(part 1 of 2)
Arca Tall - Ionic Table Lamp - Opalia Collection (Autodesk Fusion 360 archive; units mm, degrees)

design "Marble Base - Ionic Table Lamp - Ketra Ready - 120V - Opalia Collection" references "Marble Base - Ionic Table Lamp - Ketra Ready - 120V", "Ketra - A20 Tunable Lamp", "Arca Tall", "Chinois", "Arca Petite", "Trove - TL", "Facet Petite"
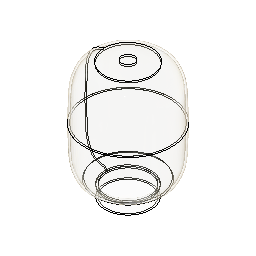
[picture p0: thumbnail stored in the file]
component_insert "Component Insert2"
component_insert "Component Insert3"
component_insert "Component Insert4"
component_insert "Component Insert5"
position "Position1"
component_insert "Component Insert6"
component_insert "Component Insert7"
component_insert "Component Insert8"

design "Arca Petite"
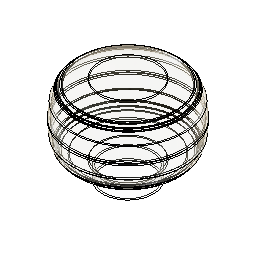
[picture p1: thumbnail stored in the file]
sketch "Sketch1" plane through (0, 0, 0) normal (0, 1, 0) x axis (1, 0, 0)
  line L1 (0, 101.6) -> (0, -101.6)
  line L2 (127, 0) -> (-127, 0)
  line L3 (63.5, 101.6) -> (-63.5, 101.6)
  perpendicular L1 L2
  parallel L2 L3
sketch "Sketch2" plane through (0, 0, 0) normal (0, 1, 0) x axis (1, 0, 0)
  line L1 (0, 101.6) -> (0, -101.6)
  line L2 (0, -76.2) -> (0, 101.6)
  line L3 (127, 0) -> (-127, 0)
  line L4 (114.3, 0) -> (-114.3, 0)
  line L5 (50.8, 101.6) -> (50.8, 63.5)
  line L6 (-50.8, 101.6) -> (50.8, 101.6)
  line L7 (-50.8, 63.5) -> (-50.8, 101.6)
  line L8 (63.5, 101.6) -> (-63.5, 101.6)
  line L9 (114.3, -76.2) -> (114.3, 63.5)
  line L10 (-114.3, -76.2) -> (114.3, -76.2)
  line L11 (-114.3, 63.5) -> (-114.3, -76.2)
  line L12 (-50.8, 63.5) -> (-114.3, 63.5)
  line L13 (114.3, 63.5) -> (50.8, 63.5)
  point P2 (0, 101.6)
  point P5 (0, 101.6)
  point P6 (0, -76.2)
  point P9 (-114.3, 0)
  point P10 (114.3, 0)
  point P11 (50.8, 101.6)
  point P19 (50.8, 63.5)
  coincident P2 P5
  coincident L1 P6
  coincident L3 P9
  coincident L3 P10
  vertical L5
  horizontal L6
  vertical L7
  coincident P11 L8
  horizontal L12
  vertical L9
  horizontal L10
  vertical L11
  coincident P19 L12
  collinear L12 L13
derived_base_feature "Derived Base Feature"
revolve "Revolve1" sketch "Sketch4" AlongAngle 360 bodies "Arca Petite"
shell "Shell1" innerThickness 3.81
component_from_bodies "Body->Comp"
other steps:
base_feature "Base Feature" bodies "Arca Petite"
create_component "CreateComponent1"
remove_body "RemoveBody1"
named bodies: "Arca Petite"

design "Neoprene Pad"
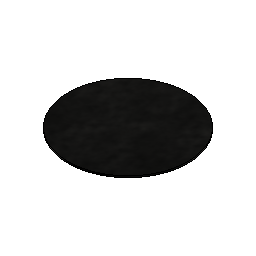
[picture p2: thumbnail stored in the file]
sketch "Sketch1" plane through (0, 0, 0) normal (0, 0, 1) x axis (1, 0, 0)
  circle C1 centre (0, 0) radius 57.15
  point P1 (0, 0)
  point P2 (0, 0)
  coincident P1 P2
extrude "Extrude1" new body sketch "Sketch1" along normal blind 1.5875 bodies "Neoprene Pad"
component_from_bodies "Body->Comp"
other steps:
base_feature "Base Feature" bodies "Neoprene Pad"
create_component "CreateComponent1"
remove_body "RemoveBody1"
named bodies: "Neoprene Pad"

design "T9 - Bulb"
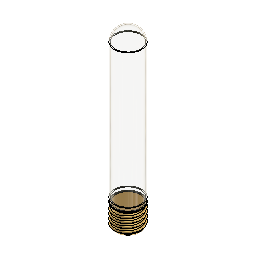
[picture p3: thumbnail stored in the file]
sketch "Sketch1" plane through (0, 0, 0) normal (0, 1, 0) x axis (1, 0, 0)
  line L1 (0, -166.37) -> (0, 0)
  line L2 (13.97, -13.97) -> (13.97, -152.4)
  line L3 (-13.97, -152.4) -> (-13.97, -13.97)
  line L4 (0, 0) -> (0, -166.37)
  line L5 (12.97, -13.97) -> (12.97, -152.4)
  line L6 (-12.97, -152.4) -> (-12.97, -13.97)
  line L7 (-12.3978, -10.16) -> (-13.4404, -10.16)
  line L8 (13.4404, -10.16) -> (12.3978, -10.16)
  arc A1 centre (0, -152.4) radius 13.97 clockwise from (13.97, -152.4) to (-13.97, -152.4)
  arc A2 centre (0, -152.4) radius 12.97 clockwise from (12.97, -152.4) to (-12.97, -152.4)
  arc A3 centre (0, -13.97) radius 13.97 clockwise from (13.4404, -10.16) to (13.97, -13.97)
  arc A4 centre (0, -13.97) radius 13.97 clockwise from (-13.97, -13.97) to (-13.4404, -10.16)
  arc A5 centre (0, -13.97) radius 12.97 clockwise from (12.3978, -10.16) to (12.97, -13.97)
  arc A6 centre (0, -13.97) radius 12.97 clockwise from (-12.97, -13.97) to (-12.3978, -10.16)
  point P1 (0, 0)
  point P2 (0, 0)
  point P3 (0, -166.37)
  point P10 (0, 0)
  point P17 (13.4404, -10.16)
  point P19 (12.3978, -10.16)
  point P4 (13.97, -152.4)
  point P5 (13.97, -13.97)
  coincident P1 P2
  vertical L1
  tangent L2 A3
  tangent L3 A3
  parallel L2 L3
  tangent L3 A1
  tangent L2 A1
  midpoint P3 A1
  coincident P1 P10
  perpendicular L1 L7
  coincident P17 L7
  concentric A3 A4
  coincident P10 A3
  concentric A1 A2
  tangent L5 A2
  tangent L5 A5
  tangent L6 A5
  tangent L6 A2
  coincident P19 L7
  concentric A5 A6
  collinear L7 L8
  dimension "d6" distance L2 L3 = 27.94
  dimension "d7" distance P4 P5 = 138.43
revolve "Revolve1" sketch "Sketch1" AlongAngle 360 bodies "T9"
derived_base_feature "Derived Base Feature" bodies "E26 Base"
align "Align1"
move "Move1"
component_from_bodies "Body->Comp1"
component_from_bodies "Body->Comp2"
copy_paste "CutPaste1"
copy_paste "CutPaste2"
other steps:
base_feature "Base Feature1" bodies "T9"
base_feature "Base Feature1" bodies "E26 Base"
create_component "CreateComponent1"
create_component "CreateComponent2"
remove_body "RemoveBody1"
create_component "CreateComponent3"
remove_body "RemoveBody2"
remove_instance "RemoveInstance1"
remove_instance "RemoveInstance2"
named bodies: "T9", "E26 Base"

design "Marble Base - Silicone Gasket"
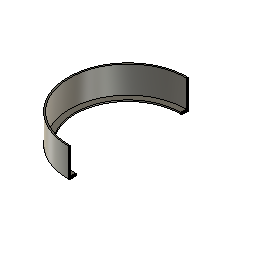
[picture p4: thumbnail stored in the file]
sketch "Sketch1" plane through (0, 0, 0) normal (0, 0, 1) x axis (1, 0, 0)
  circle C1 centre (0, 0) radius 53.34
  point P1 (0, 0)
  point P2 (0, 0)
  coincident P1 P2
extrude "Extrude1" new body sketch "Sketch1" along normal blind 25.4 bodies "Silicone Gasket"
shell "Shell1" innerThickness 1.27
sketch "Sketch2" plane through (0, 0, 1.27) normal (0, 0, 1) x axis (-1, 0, 0)
  circle C1 centre (0, 0) radius 52.07
  circle C2 centre (0, 0) radius 46.99
  concentric C1 C2
extrude "Extrude2" cut sketch "Sketch2" profile of C2 against normal blind 12.7
component_from_bodies "Body->Comp"
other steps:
base_feature "Base Feature" bodies "Silicone Gasket"
create_component "CreateComponent1"
remove_body "RemoveBody1"
named bodies: "Silicone Gasket"

design "2-Pole Plug End"
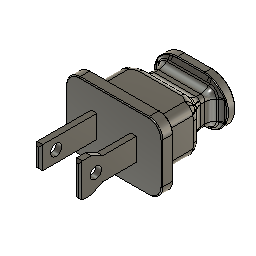
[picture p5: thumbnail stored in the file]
sketch "Sketch1" plane through (0, 0, 0) normal (0, 1, 0) x axis (1, 0, 0)
  line L1 (9.6837, 9.525) -> (-9.6837, 9.525)
  line L2 (13.4938, -5.715) -> (13.4938, 5.715)
  line L3 (-9.6837, -9.525) -> (9.6837, -9.525)
  line L4 (-13.4937, 5.715) -> (-13.4937, -5.715)
  line L5 (13.4938, -9.525) -> (-13.4937, 9.525)
  line L6 (-13.4937, -9.525) -> (13.4938, 9.525)
  arc A1 centre (-9.6837, -5.715) radius 3.81 clockwise from (-9.6837, -9.525) to (-13.4937, -5.715)
  arc A2 centre (9.6837, -5.715) radius 3.81 clockwise from (13.4938, -5.715) to (9.6837, -9.525)
  arc A3 centre (9.6837, 5.715) radius 3.81 clockwise from (9.6837, 9.525) to (13.4938, 5.715)
  arc A4 centre (-9.6837, 5.715) radius 3.81 clockwise from (-13.4937, 5.715) to (-9.6837, 9.525)
  point P6 (0, 0)
  point P1 (0, 0)
  point P5 (-13.4937, -9.525)
  point P4 (13.4938, -9.525)
  point P3 (13.4938, 9.525)
  point P2 (-13.4937, 9.525)
  horizontal L1
  perpendicular L1 L2
  parallel L1 L3
  parallel L2 L4
  coincident L5 P6
  coincident L6 P6
  coincident P1 P6
  coincident P5 L4
  coincident P5 L3
  tangent L4 A1
  tangent L3 A1
  coincident P4 L3
  coincident P4 L2
  tangent L3 A2
  tangent L2 A2
  equal A1 A2
  coincident P3 L2
  coincident P3 L1
  tangent L2 A3
  tangent L1 A3
  equal A1 A3
  coincident P2 L1
  coincident P2 L4
  tangent L1 A4
  tangent L4 A4
  equal A1 A4
  dimension "d1" distance P4 P5 = 26.9875
  dimension "d2" distance P2 P5 = 19.05
  dimension "d3" radius A1 = 3.81
extrude "Extrude1" new body sketch "Sketch1" profile of L1 L2 L3 L4 A1 A2 A3 A4 along normal blind 3.175
sketch "Sketch2" plane through (0, 3.175, 0) normal (0, 1, 0) x axis (-1, 0, 0)
  line L1 (9.6837, -9.525) -> (-9.6837, -9.525)
  line L2 (13.4937, 5.715) -> (13.4937, -5.715)
  line L3 (-9.6837, 9.525) -> (9.6837, 9.525)
  line L4 (-13.4938, -5.715) -> (-13.4938, 5.715)
  line L5 (10.16, -6.35) -> (-10.16, -6.35)
  line L6 (10.16, 6.35) -> (10.16, -6.35)
  line L7 (-10.16, 6.35) -> (10.16, 6.35)
  line L8 (-10.16, -6.35) -> (-10.16, 6.35)
  line L9 (10.16, 6.35) -> (-10.16, -6.35)
  line L10 (-10.16, 6.35) -> (10.16, -6.35)
  arc A1 centre (-9.6837, -5.715) radius 3.81 clockwise from (-9.6837, -9.525) to (-13.4938, -5.715)
  arc A2 centre (9.6837, -5.715) radius 3.81 clockwise from (13.4937, -5.715) to (9.6837, -9.525)
  arc A3 centre (9.6837, 5.715) radius 3.81 clockwise from (9.6837, 9.525) to (13.4937, 5.715)
  arc A4 centre (-9.6837, 5.715) radius 3.81 clockwise from (-13.4938, 5.715) to (-9.6837, 9.525)
  point P18 (0, 0)
  point P1 (0, 0)
  horizontal L5
  perpendicular L5 L6
  parallel L5 L7
  parallel L6 L8
  coincident L9 P18
  coincident L10 P18
  coincident P1 P18
extrude "Extrude2" add sketch "Sketch2" profile of L5 L6 L7 L8 along normal blind 9.525
sketch "Sketch3" plane through (0, 12.7, 0) normal (0, 1, 0) x axis (-1, 0, 0)
  line L1 (-10.16, -6.35) -> (-10.16, 6.35)
  line L2 (10.16, -6.35) -> (-10.16, -6.35)
  line L3 (10.16, 6.35) -> (10.16, -6.35)
  line L4 (-10.16, 6.35) -> (10.16, 6.35)
  line L5 (-7.1437, 3.9688) -> (7.1437, 3.9688)
  line L6 (-7.1437, -3.9688) -> (-7.1437, 3.9688)
  line L7 (7.1437, -3.9688) -> (-7.1437, -3.9688)
  line L8 (7.1437, 3.9688) -> (7.1437, -3.9688)
  line L9 (-7.1437, -3.9688) -> (7.1437, 3.9688)
  line L10 (7.1437, -3.9688) -> (-7.1437, 3.9688)
  point P10 (0, 0)
  point P1 (0, 0)
  point P8 (-7.1437, -3.9688)
  point P9 (7.1437, -3.9688)
  point P7 (-7.1437, 3.9688)
  horizontal L5
  perpendicular L5 L6
  parallel L5 L7
  parallel L6 L8
  coincident L9 P10
  coincident L10 P10
  coincident P1 P10
  dimension "d8" distance P8 P9 = 14.2875
  dimension "d9" distance P7 P8 = 7.9375
extrude "Extrude3" add sketch "Sketch3" profile of L5 L6 L7 L8 along normal blind 11.1125
fillet "Fillet1" radius 2.286 1.27 0.254
chamfer "Chamfer1" distance 3.429
fillet "Fillet2" radius 2.54 1.905
sketch "Sketch4" plane through (0, 23.8125, 0) normal (0, 1, 0) x axis (-1, 0, 0)
  line L1 (-7.1437, -2.6987) -> (-7.1437, 2.6987)
  line L2 (5.8737, -3.9688) -> (-5.8737, -3.9688)
  line L3 (7.1437, 2.6987) -> (7.1437, -2.6987)
  line L4 (-5.8737, 3.9688) -> (5.8737, 3.9688)
  line L5 (-3.81, 6.604) -> (3.81, 6.604)
  line L6 (3.81, -6.604) -> (-3.81, -6.604)
  line L7 (-10.414, 0) -> (10.414, 0)
  arc A1 centre (-5.8737, 2.6987) radius 1.27 clockwise from (-7.1437, 2.6987) to (-5.8737, 3.9688)
  arc A2 centre (-5.8737, -2.6987) radius 1.27 clockwise from (-5.8737, -3.9688) to (-7.1437, -2.6987)
  arc A3 centre (5.8737, -2.6987) radius 1.27 clockwise from (7.1437, -2.6987) to (5.8737, -3.9688)
  arc A4 centre (5.8737, 2.6987) radius 1.27 clockwise from (5.8737, 3.9688) to (7.1437, 2.6987)
  arc A5 centre (-3.81, 0) radius 6.604 clockwise from (-3.81, -6.604) to (-3.81, 6.604)
  arc A6 centre (3.81, 0) radius 6.604 clockwise from (3.81, 6.604) to (3.81, -6.604)
  point P20 (10.414, 0)
  point P21 (-10.414, 0)
  tangent L5 A5
  tangent A5 L6
  parallel L5 L6
  tangent L6 A6
  tangent L5 A6
  midpoint A6 P20
  midpoint A5 P21
  perpendicular L1 L7
extrude "Extrude4" add sketch "Sketch4" profile of A1 L1 A2 L2 A3 L3 A4 L4 L5 A5 L6 A6 against normal blind 2.286
chamfer "Chamfer2" distance 1.778
fillet "Fillet3" radius 1.778
fillet "Fillet4" radius 0.254
fillet "Fillet5" radius 0.254
fillet "Fillet6" radius 0.254
fillet "Fillet7" radius 3.175
sketch "Sketch5" plane through (0, 0, 0) normal (0, -1, 0) x axis (1, 0, 0)
  line L1 (-13.2397, -5.715) -> (-13.2397, 5.715)
  line L2 (9.6837, -9.271) -> (-9.6837, -9.271)
  line L3 (13.2397, 5.715) -> (13.2397, -5.715)
  line L4 (-9.6837, 9.271) -> (9.6837, 9.271)
  line L5 (-6.35, -3.175) -> (-6.35, 3.175)
  line L6 (6.35, 3.175) -> (-6.35, -3.175)
  line L7 (-6.35, 3.175) -> (6.35, -3.175)
  line L8 (-4.7625, 3.175) -> (-6.35, 3.175)
  line L9 (-4.7625, -3.175) -> (-4.7625, 3.175)
  line L10 (-6.35, -3.175) -> (-4.7625, -3.175)
  line L11 (-6.35, 3.175) -> (-6.35, -3.175)
  line L12 (0, -3.302) -> (0, 3.81)
  line L13 (4.7625, -3.175) -> (4.7625, 3.175)
  line L14 (4.7625, 3.175) -> (6.35, 3.175)
  line L15 (6.35, -3.175) -> (6.35, 3.175)
  line L16 (6.35, -3.175) -> (4.7625, -3.175)
  arc A1 centre (-9.6837, 5.715) radius 3.556 clockwise from (-13.2397, 5.715) to (-9.6837, 9.271)
  arc A2 centre (-9.6837, -5.715) radius 3.556 clockwise from (-9.6837, -9.271) to (-13.2397, -5.715)
  arc A3 centre (9.6837, -5.715) radius 3.556 clockwise from (13.2397, -5.715) to (9.6837, -9.271)
  arc A4 centre (9.6837, 5.715) radius 3.556 clockwise from (9.6837, 9.271) to (13.2397, 5.715)
  point P18 (0, 0)
  point P1 (0, 0)
  point P14 (-6.35, -3.175)
  point P27 (6.35, -3.175)
  point P17 (-6.35, 3.175)
  point P26 (6.35, 3.175)
  point P19 (-4.7625, 3.175)
  point P24 (4.7625, 3.175)
  point P20 (-4.7625, -3.175)
  point P25 (4.7625, -3.175)
  point P21 (-6.35, -3.175)
  point P28 (6.35, -3.175)
  point P15 (6.35, -3.175)
  point P16 (6.35, 3.175)
  coincident L6 P18
  coincident L7 P18
  coincident P1 P18
  horizontal L8
  vertical L9
  horizontal L10
  vertical L11
  vertical L12
  symmetric P14 L12 P27
  symmetric P17 L12 P26
  symmetric P19 L12 P24
  symmetric P20 L12 P25
  symmetric P21 L12 P28
  dimension "d36" distance P15 P16 = 6.35
  dimension "d37" distance P17 P19 = 1.5875
extrude "Extrude5" add sketch "Sketch5" profile of L5 L8 L9 L10 L11 L13 L14 L15 L16 along normal blind 15.875
sketch "Sketch7" plane through (0, 0, 3.175) normal (0, 0, 1) x axis (-1, 0, 0)
  line L1 (-4.7625, 0) -> (-6.35, 0)
  line L2 (-4.7625, 15.875) -> (-4.7625, 0)
  line L3 (-6.35, 15.875) -> (-4.7625, 15.875)
  line L4 (-6.35, 0) -> (-6.35, 15.875)
  line L5 (-4.7625, 15.875) -> (-6.35, 15.875)
  line L6 (-4.7625, 9.525) -> (-4.7625, 15.875)
  line L7 (-6.35, 9.525) -> (-4.7625, 9.525)
  line L8 (-6.35, 15.875) -> (-6.35, 9.525)
  point P5 (-6.35, 15.875)
  point P6 (-6.35, 15.875)
  point P9 (-6.35, 9.525)
  horizontal L5
  vertical L6
  horizontal L7
  vertical L8
  coincident P5 P6
  dimension "d45" distance P6 P9 = 6.35
extrude "Extrude7" add sketch "Sketch7" profile of L2 L3 L4 L5 L6 L7 L8 against normal blind 7.9375 and along normal blind 1.5875
chamfer "Chamfer3" distance 0.508
chamfer "Chamfer4" distance 0.635 distance 0.635
sketch "Sketch6" plane through (6.35, 0, 0) normal (1, 0, 0) x axis (0, 1, 0)
  line L1 (0, -3.175) -> (-9.525, -3.175)
  line L2 (0, 3.175) -> (0, -3.175)
  line L3 (-9.525, 3.175) -> (0, 3.175)
  line L4 (-15.367, -4.6355) -> (-15.367, 4.6355)
  line L5 (-11.43, 0) -> (-16.002, 0)
  line L6 (-9.525, -4.7625) -> (-15.24, -4.7625)
  line L7 (-9.525, -3.175) -> (-9.525, -4.7625)
  line L8 (-9.525, 4.7625) -> (-9.525, 3.175)
  line L9 (-15.24, 4.7625) -> (-9.525, 4.7625)
  line L10 (-15.24, -4.7625) -> (-15.367, -4.6355)
  line L11 (-15.367, 4.6355) -> (-15.24, 4.7625)
  circle C1 centre (-11.43, 0) radius 1.5875
  point P9 (-11.43, 0)
  point P10 (-11.43, 0)
  perpendicular L4 L5
  coincident P9 P10
  dimension "d42" diameter C1 = 3.175
extrude "Extrude6" cut sketch "Sketch6" profile of C1 against normal blind 20.32
chamfer "Chamfer5" distance 3.175 distance 1.5875 distance 3.175 distance 1.5875
component_from_bodies "Body->Comp"
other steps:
base_feature "Base Feature" bodies "2-Pole Plug End"
create_component "CreateComponent1"
remove_body "RemoveBody1"
named bodies: "2-Pole Plug End"

design "Facet Petite"
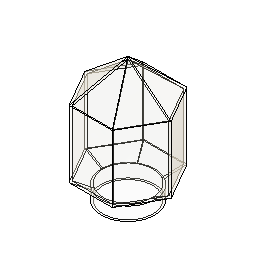
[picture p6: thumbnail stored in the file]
sketch "Sketch7" plane through (0, 0, 0) normal (1, 0, 0) x axis (0, 1, 0)
sketch "Sketch8" plane through (0, 0, 0) normal (0, 0, 1) x axis (1, 0, 0)
  circle C1 centre (0, 0) radius 50.8
  point P1 (0, 0)
  point P2 (0, 0)
  coincident P1 P2
  dimension "d17" diameter C1 = 101.6
extrude "Extrude5" new body sketch "Sketch8" along normal blind 25.4 and against normal blind 25.4
work_plane "WorkPlane1" AlongDistance 17.78
sketch "Sketch10" plane through (0, 0, 25.4) normal (0, 0, 1) x axis (-1, 0, 0)
  circle C1 centre (0, 0) radius 50.8
sketch "Sketch12" plane through (0, 0, 43.18) normal (0, 0, 1) x axis (1, 0, 0)
  line L1 (-82.1223, 0) -> (-41.0612, 71.12)
  line L2 (-41.0612, -71.12) -> (-82.1223, 0)
  line L3 (41.0612, -71.12) -> (-41.0612, -71.12)
  line L4 (82.1223, 0) -> (41.0612, -71.12)
  line L5 (41.0612, 71.12) -> (82.1223, 0)
  line L6 (-41.0612, 71.12) -> (41.0612, 71.12)
  point P1 (0, 0)
  point P8 (0, 0)
  coincident P1 P8
  dimension "d22" distance P8 L6 = 71.12
sketch "Sketch15" plane through (0, 0, 0) normal (0, 1, 0) x axis (1, 0, 0)
  line L1 (53.7365, -21.6801) -> (82.1223, -43.18)
  line L2 (-50.8, -25.4) -> (-82.1223, -43.18)
  point P2 (82.1223, -43.18)
  point P3 (82.1223, -43.18)
  point P5 (-82.1223, -43.18)
  point P7 (-82.1223, -43.18)
  point P6 (-50.8, -25.4)
  point P8 (-50.8, -25.4)
  coincident P2 P3
  coincident P5 P7
  coincident P6 P8
sketch "Sketch17" plane through (0, 0, 25.4) normal (0, 0, 1) x axis (-1, 0, 0)
  line L1 (51.3255, 0) -> (0, 0)
  line L2 (73.3235, 0) -> (0, 0)
  line L3 (-41.0612, -71.12) -> (-25.4, -43.9941)
  line L4 (-36.6617, -63.5) -> (-25.4, -43.9941)
  line L5 (78.4305, 0) -> (0, 0)
  line L6 (41.0612, -71.12) -> (25.4, -43.9941)
  line L7 (25.4, 43.9941) -> (41.0612, 71.12)
  line L8 (73.3235, 0) -> (0, 0)
  line L9 (-25.4, 43.9941) -> (-41.0612, 71.12)
  line L10 (0, 0) -> (0, 0)
  circle C1 centre (0, 0) radius 50.8
  point P1 (0, 0)
  point P4 (0, 0)
  point P2 (-41.0612, -71.12)
  point P6 (-41.0612, -71.12)
  point P3 (0, 0)
  point P7 (0, 0)
  point P9 (-25.4, -43.9941)
  point P12 (41.0612, -71.12)
  point P13 (41.0612, -71.12)
  point P15 (25.4, -43.9941)
  point P16 (41.0612, 71.12)
  point P17 (41.0612, 71.12)
  point P18 (25.4, 43.9941)
  point P19 (-41.0612, 71.12)
  point P20 (-41.0612, 71.12)
  point P21 (0, 0)
  point P23 (-25.4, 43.9941)
  point P25 (0, 0)
  point P24 (0, 0)
  point P26 (0, 0)
  horizontal L1
  coincident P1 P4
  coincident P2 P6
  horizontal L2
  coincident P3 P7
  coincident C1 P9
  coincident P12 P13
  horizontal L5
  coincident C1 P15
  coincident P16 P17
  coincident C1 P18
  coincident P19 P20
  horizontal L8
  coincident P1 P21
  coincident C1 P23
  coincident P1 P25
  coincident P24 P26
extrude "Extrude6" new body sketch "Sketch12" along normal blind 127
work_plane "WorkPlane2" AlongDistance 66.04
sketch "Sketch18" plane through (0, 0, 236.22) normal (0, 0, 1) x axis (1, 0, 0)
  line L1 (41.0612, -71.12) -> (0, 0)
  line L2 (82.1223, 0) -> (0, 0)
  line L3 (41.0612, 71.12) -> (0, 0)
  line L4 (-41.0612, 71.12) -> (0, 0)
  line L5 (-82.1223, 0) -> (0, 0)
  line L6 (-41.0612, -71.12) -> (0, 0)
  point P1 (0, 0)
  point P3 (0, 0)
  point P2 (41.0612, -71.12)
  point P4 (41.0612, -71.12)
  point P6 (0, 0)
  point P5 (82.1223, 0)
  point P7 (82.1223, 0)
  point P9 (0, 0)
  point P8 (41.0612, 71.12)
  point P10 (41.0612, 71.12)
  point P12 (0, 0)
  point P11 (-41.0612, 71.12)
  point P13 (-41.0612, 71.12)
  point P15 (0, 0)
  point P14 (-82.1223, 0)
  point P16 (-82.1223, 0)
  point P18 (0, 0)
  point P17 (-41.0612, -71.12)
  point P19 (-41.0612, -71.12)
  coincident P1 P3
  coincident P2 P4
  coincident P1 P6
  coincident P5 P7
  coincident P1 P9
  coincident P8 P10
  coincident P1 P12
  coincident P11 P13
  coincident P1 P15
  coincident P14 P16
  coincident P1 P18
  coincident P17 P19
loft "Loft1"
loft "Loft2" sketch "Sketch17"
component_from_bodies "Body->Comp"
extrude "Extrude1" cut of existing geometry blind -25.4
shell "Shell2" innerThickness 3.81
fillet "Fillet1" radius 7.62
fillet "Fillet2" radius 6.35
fillet "Fillet3" radius 6.35
fillet "Fillet4" radius 6.35
fillet "Fillet5" radius 6.35
fillet "Fillet6" radius 6.35
fillet "Fillet7" radius 3.81
fillet "Fillet8" radius 6.35
fillet "Fillet9" radius 6.35
fillet "Fillet10" radius 6.35
fillet "Fillet11" radius 6.35
fillet "Fillet12" radius 6.35
fillet "Fillet13" radius 2.286
shell "Shell1" innerThickness 2.54
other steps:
base_feature "Base Feature"
create_component "CreateComponent3"
remove_body "RemoveBody2"

design "Chinois"
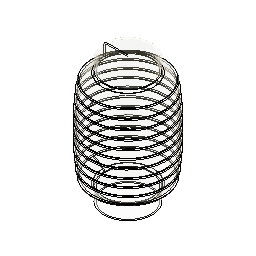
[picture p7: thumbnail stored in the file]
named bodies: "Chinois"

design "Marble Base - Plastic Insert"
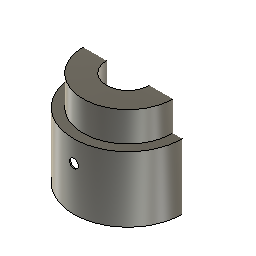
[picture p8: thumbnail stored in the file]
sketch "Sketch1" plane through (0, 0, 0) normal (0, 0, 1) x axis (1, 0, 0)
  circle C1 centre (0, 0) radius 50.038
  point P1 (0, 0)
  point P2 (0, 0)
  coincident P1 P2
  dimension "d1" diameter C1 = 100.076
extrude "Extrude1" new body sketch "Sketch1" along normal blind 72.898 bodies "Plastic Insert"
shell "Shell1" innerThickness 1.016
work_plane "WorkPlane1" AlongDistance 18.034
sketch "Sketch2" plane through (0, 0, 90.932) normal (0, 0, 1) x axis (1, 0, 0)
  circle C1 centre (0, 0) radius 20.701
  point P1 (0, 0)
  point P2 (0, 0)
  coincident P1 P2
  dimension "d6" diameter C1 = 41.402
extrude "Extrude2" add sketch "Sketch2" against normal blind 65.024
shell "Shell2" innerThickness 1.016
sketch "Sketch3" plane through (0, 0, 0) normal (0, 1, 0) x axis (1, 0, 0)
  line L1 (5.08, -20.32) -> (-5.08, -20.32)
  line L2 (5.08, 20.32) -> (5.08, -20.32)
  line L3 (-5.08, 20.32) -> (5.08, 20.32)
  line L4 (-5.08, -20.32) -> (-5.08, 20.32)
  line L5 (5.08, 20.32) -> (-5.08, -20.32)
  line L6 (-5.08, 20.32) -> (5.08, -20.32)
  point P6 (0, 0)
  point P1 (0, 0)
  horizontal L1
  perpendicular L1 L2
  parallel L1 L3
  parallel L2 L4
  coincident L5 P6
  coincident L6 P6
  coincident P1 P6
extrude "Extrude3" cut sketch "Sketch3" profile of L1 L2 L3 L4 along normal blind 91.44
sketch "Sketch4" plane through (0, 0, 0) normal (0, 1, 0) x axis (1, 0, 0)
  line L1 (0, -40.64) -> (0, 0)
  circle C1 centre (0, -40.64) radius 4.064
  point P1 (0, 0)
  point P2 (0, 0)
  point P3 (0, -40.64)
  point P4 (0, -40.64)
  coincident P1 P2
  vertical L1
  coincident P3 P4
  dimension "d12" diameter C1 = 8.128
work_plane "WorkPlane2" AlongDistance -91.44
sketch "Sketch5" plane through (0, -91.44, 0) normal (0, 1, 0) x axis (1, 0, 0)
  circle C1 centre (0, -40.64) radius 4.064
extrude "Extrude4" cut sketch "Sketch5" along normal blind 63.5
sketch "Sketch6" plane through (0, 0, 26.924) normal (0, 0, 1) x axis (-1, 0, 0)
  circle C1 centre (0, 0) radius 19.685
  circle C2 centre (0, 0) radius 5.461
  concentric C1 C2
  dimension "d16" diameter C2 = 10.922
extrude "Extrude5" cut sketch "Sketch6" profile of C2 against normal blind 15.24
sketch "Sketch7" plane through (0, 0, 72.898) normal (0, 0, 1) x axis (-1, 0, 0)
  circle C1 centre (0, 0) radius 20.701
  circle C2 centre (0, 0) radius 50.038
  circle C3 centre (0, 0) radius 20.701
  circle C4 centre (0, 0) radius 45.72
  point P1 (0, 0)
  point P3 (0, 0)
  point P4 (0, 0)
  coincident P1 P3
  coincident P1 P4
extrude "Extrude6" add sketch "Sketch7" profile of C1 C3 C4 along normal blind 18.034
sketch "Sketch8" plane through (0, 0, 71.882) normal (0, 0, -1) x axis (1, 0, 0)
  circle C1 centre (0, 0) radius 20.701
  circle C2 centre (0, 0) radius 49.022
  circle C3 centre (0, 0) radius 20.701
  circle C4 centre (0, 0) radius 44.704
  point P1 (0, 0)
  point P3 (0, 0)
  point P4 (0, 0)
  coincident P1 P3
  coincident P1 P4
  dimension "d21" diameter C4 = 89.408
extrude "Extrude7" cut sketch "Sketch8" profile of C1 C3 C4 against normal blind 17.78
extrude "Extrude8" add of existing geometry blind 9.398
extrude "Extrude9" cut of existing geometry blind -9.398
component_from_bodies "Body->Comp"
offset_faces "OffsetFaces1" distance 4.445
offset_faces "OffsetFaces2" distance -4.445
offset_faces "OffsetFaces3" distance 3.175
offset_faces "OffsetFaces4" distance 3.175
offset_faces "OffsetFaces5" distance 3.175
offset_faces "OffsetFaces6" distance -3.175
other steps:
base_feature "Base Feature" bodies "Plastic Insert"
create_component "CreateComponent1"
remove_body "RemoveBody1"
named bodies: "Plastic Insert"

design "Arca Tall"
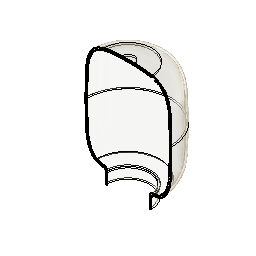
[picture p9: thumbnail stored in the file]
derived_base_feature "Derived Base Feature" bodies "Balon"
work_plane "WorkPlane1" AlongDistance 0
sketch "Sketch1" plane through (0, 0, 0) normal (0, 1, 0) x axis (1, 0, 0)
  line L1 (0, 317.5) -> (0, 2.9083)
  curve K1 (-82.9821, 124.2212) -> (-50.8, 237.8015)
  curve K2 (-51.0925, 237.681) -> (-50.8, 237.8015)
  curve K3 (-51.3855, 237.5558) -> (-51.0925, 237.681)
  curve K4 (-54.7608, 236.0513) -> (-51.3855, 237.5558)
  curve K5 (-57.9615, 234.05) -> (-54.7608, 236.0513)
  curve K6 (-67.2727, 226.749) -> (-57.9615, 234.05)
  curve K7 (-69.0552, 224.2615) -> (-67.2727, 226.749)
  curve K8 (-72.1872, 218.7832) -> (-69.0552, 224.2615)
  curve K9 (-74.1213, 215.1556) -> (-72.1872, 218.7832)
  curve K10 (-78.3031, 204.3965) -> (-74.1213, 215.1556)
  curve K11 (-79.7275, 197.3397) -> (-78.3031, 204.3965)
  curve K12 (-81.3333, 185.4664) -> (-79.7275, 197.3397)
  curve K13 (-81.6254, 178.4008) -> (-81.3333, 185.4664)
  curve K14 (-82.49, 152.2133) -> (-81.6254, 178.4008)
  curve K15 (-82.9821, 136.067) -> (-82.49, 152.2133)
  curve K16 (-82.9821, 124.2212) -> (-82.9821, 136.067)
  curve K17 (50.8, 237.7999) -> (82.9821, 124.2212)
  curve K18 (82.9821, 140.3031) -> (82.9821, 124.2212)
  curve K19 (81.9353, 169.4257) -> (82.9821, 140.3031)
  curve K20 (81.3621, 183.6489) -> (81.9353, 169.4257)
  curve K21 (80.9478, 189.8724) -> (81.3621, 183.6489)
  curve K22 (77.8147, 206.9858) -> (80.9478, 189.8724)
  curve K23 (74.9652, 213.2153) -> (77.8147, 206.9858)
  curve K24 (69.4688, 224.1531) -> (74.9652, 213.2153)
  curve K25 (67.2512, 226.458) -> (69.4688, 224.1531)
  curve K26 (61.5696, 231.3138) -> (67.2512, 226.458)
  curve K27 (57.377, 234.6711) -> (61.5696, 231.3138)
  curve K28 (52.0556, 237.2628) -> (57.377, 234.6711)
  curve K29 (51.4313, 237.5413) -> (52.0556, 237.2628)
  curve K30 (50.8, 237.7999) -> (51.4313, 237.5413)
  line L2 (-50.8, 317.5) -> (-50.8, 237.8015)
  line L3 (50.8, 317.5) -> (50.8, 237.7999)
  line L4 (-19.0713, 6.7501) -> (-19.0713, 6.7501)
  curve K31 (82.9821, 124.1958) -> (40.1509, 7.3012)
  curve K32 (41.8198, 7.6176) -> (40.1509, 7.3012)
  curve K33 (43.2113, 8.0663) -> (41.8198, 7.6176)
  curve K34 (47.0139, 9.2854) -> (43.2113, 8.0663)
  curve K35 (47.3314, 9.3805) -> (47.0139, 9.2854)
  curve K36 (50.1192, 10.3272) -> (47.3314, 9.3805)
  curve K37 (51.833, 11.0085) -> (50.1192, 10.3272)
  curve K38 (57.8313, 14.1895) -> (51.833, 11.0085)
  curve K39 (61.4491, 17.0488) -> (57.8313, 14.1895)
  curve K40 (66.8203, 21.5867) -> (61.4491, 17.0488)
  curve K41 (68.5372, 23.5528) -> (66.8203, 21.5867)
  curve K42 (71.2201, 27.8971) -> (68.5372, 23.5528)
  curve K43 (74.7424, 33.8984) -> (71.2201, 27.8971)
  curve K44 (78.2342, 44.8406) -> (74.7424, 33.8984)
  curve K45 (79.6792, 50.3463) -> (78.2342, 44.8406)
  curve K46 (81.3558, 63.5576) -> (79.6792, 50.3463)
  curve K47 (81.6386, 70.4415) -> (81.3558, 63.5576)
  curve K48 (82.4897, 96.2198) -> (81.6386, 70.4415)
  curve K49 (82.9814, 112.3523) -> (82.4897, 96.2198)
  curve K50 (82.9821, 124.1958) -> (82.9814, 112.3523)
  curve K51 (-40.1501, 7.301) -> (-82.9821, 124.1958)
  curve K52 (-82.9813, 110.5256) -> (-82.9821, 124.1958)
  curve K53 (-82.2545, 88.8594) -> (-82.9813, 110.5256)
  curve K54 (-81.6277, 70.519) -> (-82.2545, 88.8594)
  curve K55 (-81.3572, 64.3441) -> (-81.6277, 70.519)
  curve K56 (-79.4149, 46.8924) -> (-81.3572, 64.3441)
  curve K57 (-76.5204, 38.9768) -> (-79.4149, 46.8924)
  curve K58 (-73.5142, 32.2947) -> (-76.5204, 38.9768)
  curve K59 (-72.5556, 30.3818) -> (-73.5142, 32.2947)
  curve K60 (-69.7914, 25.3691) -> (-72.5556, 30.3818)
  curve K61 (-68.3824, 23.4028) -> (-69.7914, 25.3691)
  curve K62 (-64.5419, 19.5456) -> (-68.3824, 23.4028)
  curve K63 (-62.3002, 17.7646) -> (-64.5419, 19.5456)
  curve K64 (-53.6583, 11.1976) -> (-62.3002, 17.7646)
  curve K65 (-49.6968, 10.1396) -> (-53.6583, 11.1976)
  curve K66 (-43.4141, 8.1331) -> (-49.6968, 10.1396)
  curve K67 (-41.9704, 7.6516) -> (-43.4141, 8.1331)
  curve K68 (-40.1963, 7.3098) -> (-41.9704, 7.6516)
  curve K69 (-40.1732, 7.3054) -> (-40.1963, 7.3098)
  curve K70 (-40.1501, 7.301) -> (-40.1732, 7.3054)
  line L5 (-82.9821, 124.1958) -> (-82.9821, 124.2212)
  line L6 (82.9821, 124.2212) -> (82.9821, 124.1958)
  line L7 (0, 317.5) -> (-50.8, 317.5)
  line L8 (7.2015, 3.048) -> (0, 3.048)
  line L9 (0, 3.048) -> (-7.2015, 3.048)
  arc A1 centre (0, 188.595) radius 185.6867 clockwise from (-7.2015, 3.048) to (-40.1502, 7.301)
  arc A2 centre (0, 188.595) radius 185.6867 clockwise from (40.151, 7.3012) to (7.2015, 3.048)
  point P38 (-40.1502, 7.301)
  point P43 (40.1509, 7.3012)
  point P62 (-40.1501, 7.301)
  point P81 (40.151, 7.3012)
  point P84 (0, 3.048)
  vertical L1
  horizontal L4
  coincident P38 K51
  symmetric L1 A1 A2
  coincident A2 P43
  coincident A1 P62
  coincident K31 P81
  perpendicular L2 L7
  horizontal L8
  coincident L1 P84
  horizontal L9
revolve "Revolve1" sketch "Sketch1" AlongAngle 360
shell "Shell1" innerThickness 3.81
fillet "Fillet1" radius 6.35 bodies "Balon v3"
offset_faces "OffsetFaces1" distance -50.8
move "Move1"
move "Move2"
component_from_bodies "Body->Comp1"
component_from_bodies "Body->Comp2"
sketch "Sketch2" plane through (0, 0, 0) normal (0, 1, 0) x axis (1, 0, 0)
  line L1 (-85.5221, 124.2212) -> (-85.5221, 124.1961)
  curve K1 (-58.9057, 236.4383) -> (-50.8, 241.7989)
  curve K2 (-50.8, 241.554) -> (-50.8, 241.7989)
  curve K3 (-50.904, 240.933) -> (-50.8, 241.554)
  curve K4 (-51.2936, 240.2837) -> (-50.904, 240.933)
  curve K5 (-51.734, 239.7561) -> (-51.2936, 240.2837)
  curve K6 (-53.328, 238.5038) -> (-51.734, 239.7561)
  curve K7 (-54.0892, 238.1997) -> (-53.328, 238.5038)
  curve K8 (-58.9057, 236.4383) -> (-54.0892, 238.1997)
  curve K9 (-89.3309, 124.2212) -> (-58.9057, 236.4383)
  curve K10 (-62.6336, 234.9735) -> (-58.9057, 236.4383)
  curve K11 (-65.581, 233.1032) -> (-62.6336, 234.9735)
  curve K12 (-73.0224, 227.0019) -> (-65.581, 233.1032)
  curve K13 (-74.8981, 224.836) -> (-73.0224, 227.0019)
  curve K14 (-78.1104, 219.6097) -> (-74.8981, 224.836)
  curve K15 (-80.2663, 215.561) -> (-78.1104, 219.6097)
  curve K16 (-84.0943, 205.8277) -> (-80.2663, 215.561)
  curve K17 (-85.4655, 200.1154) -> (-84.0943, 205.8277)
  curve K18 (-87.4092, 188.5789) -> (-85.4655, 200.1154)
  curve K19 (-87.7349, 182.3889) -> (-87.4092, 188.5789)
  curve K20 (-88.4233, 165.9645) -> (-87.7349, 182.3889)
  curve K21 (-89.328, 138.6964) -> (-88.4233, 165.9645)
  curve K22 (-89.3309, 124.2212) -> (-89.328, 138.6964)
  line L2 (-89.3309, 124.1958) -> (-89.3309, 124.2212)
  curve K23 (-46.5001, 7.301) -> (-89.3309, 124.1958)
  curve K24 (-89.3314, 112.4293) -> (-89.3309, 124.1958)
  curve K25 (-88.8181, 95.3068) -> (-89.3314, 112.4293)
  curve K26 (-88.346, 81.2892) -> (-88.8181, 95.3068)
  curve K27 (-88.0298, 70.4902) -> (-88.346, 81.2892)
  curve K28 (-87.1514, 58.328) -> (-88.0298, 70.4902)
  curve K29 (-86.3326, 50.6119) -> (-87.1514, 58.328)
  curve K30 (-81.0932, 33.6688) -> (-86.3326, 50.6119)
  curve K31 (-77.3163, 27.4309) -> (-81.0932, 33.6688)
  curve K32 (-74.8955, 23.6666) -> (-77.3163, 27.4309)
  curve K33 (-73.5108, 22.0741) -> (-74.8955, 23.6666)
  curve K34 (-70.2346, 19.0457) -> (-73.5108, 22.0741)
  curve K35 (-64.8094, 14.3548) -> (-70.2346, 19.0457)
  curve K36 (-56.6696, 10.3041) -> (-64.8094, 14.3548)
  curve K37 (-54.0053, 9.483) -> (-56.6696, 10.3041)
  curve K38 (-49.1487, 7.9411) -> (-54.0053, 9.483)
  curve K39 (-48.3482, 7.6526) -> (-49.1487, 7.9411)
  curve K40 (-46.5001, 7.301) -> (-48.3482, 7.6526)
  line L3 (0, 266.7) -> (0, 0)
  line L4 (0, 3.048) -> (-7.7894, 3.048)
  line L5 (-50.8, 266.7) -> (-50.8, 241.7989)
  line L6 (0, 266.7) -> (-50.8, 266.7)
  arc A1 centre (-6.9779, 188.7329) radius 185.6867 clockwise from (-7.7894, 3.048) to (-46.5001, 7.301)
  point P1 (0, 0)
  point P44 (0, 0)
  point P46 (0, 3.048)
  point P5 (-50.8, 241.554)
  point P49 (0, 266.7)
  coincident P1 P44
  coincident L3 P46
  coincident P5 L5
  coincident L3 P49
revolve "Revolve2" sketch "Sketch2" AlongAngle 360 bodies "Balon v3"
shell "Shell2" innerThickness 3.81
component_from_bodies "Body->Comp3"
remove_instance "RemoveInstance1"
remove_instance "RemoveInstance2"
sketch "Sketch1" plane through (0, 0, 0) normal (0, 1, 0) x axis (1, 0, 0)
  line L1 (-6.35, 3.048) -> (-14.1394, 3.048)
  curve K1 (-52.8501, 7.301) -> (-95.6809, 124.1958)
  curve K2 (-95.6814, 112.4293) -> (-95.6809, 124.1958)
  curve K3 (-95.1681, 95.3068) -> (-95.6814, 112.4293)
  curve K4 (-94.696, 81.2892) -> (-95.1681, 95.3068)
  curve K5 (-94.3798, 70.4902) -> (-94.696, 81.2892)
  curve K6 (-93.5014, 58.328) -> (-94.3798, 70.4902)
  curve K7 (-92.6826, 50.6119) -> (-93.5014, 58.328)
  curve K8 (-87.4432, 33.6688) -> (-92.6826, 50.6119)
  curve K9 (-83.6663, 27.4309) -> (-87.4432, 33.6688)
  curve K10 (-81.2455, 23.6666) -> (-83.6663, 27.4309)
  curve K11 (-79.8608, 22.0741) -> (-81.2455, 23.6666)
  curve K12 (-76.5846, 19.0457) -> (-79.8608, 22.0741)
  curve K13 (-71.12, 13.97) -> (-76.5846, 19.0457)
  curve K14 (-62.23, 10.16) -> (-71.12, 13.97)
  curve K15 (-60.3553, 9.483) -> (-62.23, 10.16)
  curve K16 (-55.4987, 7.9411) -> (-60.3553, 9.483)
  curve K17 (-54.6982, 7.6526) -> (-55.4987, 7.9411)
  curve K18 (-52.8501, 7.301) -> (-54.6982, 7.6526)
  line L2 (-95.6809, 124.1958) -> (-95.6809, 124.2212)
  line L3 (0, 266.7) -> (0, 0)
  line L4 (0, 3.048) -> (-6.35, 3.048)
  line L5 (-95.6809, 124.2466) -> (-95.6809, 124.2212)
  line L6 (-50.8, 266.7) -> (-50.8, 241.7989)
  line L7 (0, 266.7) -> (-50.8, 266.7)
  curve K19 (-71.6837, 232.5587) -> (-50.8, 241.7989)
  curve K20 (-50.8, 237.8015) -> (-50.8, 241.7989)
  curve K21 (-53.6019, 236.5654) -> (-50.8, 237.8015)
  curve K22 (-59.7861, 236.0598) -> (-53.6019, 236.5654)
  curve K23 (-64.4375, 235.2772) -> (-59.7861, 236.0598)
  curve K24 (-69.8917, 233.4707) -> (-64.4375, 235.2772)
  curve K25 (-71.6837, 232.5587) -> (-69.8917, 233.4707)
  curve K26 (-71.6837, 232.5587) -> (-95.6809, 124.2466)
  curve K27 (-95.6814, 136.0132) -> (-95.6809, 124.2466)
  curve K28 (-95.1681, 153.1357) -> (-95.6814, 136.0132)
  curve K29 (-94.696, 167.1533) -> (-95.1681, 153.1357)
  curve K30 (-94.3798, 177.9523) -> (-94.696, 167.1533)
  curve K31 (-93.5014, 190.1145) -> (-94.3798, 177.9523)
  curve K32 (-92.6826, 197.8306) -> (-93.5014, 190.1145)
  curve K33 (-87.4432, 214.7737) -> (-92.6826, 197.8306)
  curve K34 (-83.6663, 221.0115) -> (-87.4432, 214.7737)
  curve K35 (-81.2455, 224.7759) -> (-83.6663, 221.0115)
  curve K36 (-79.8608, 226.3684) -> (-81.2455, 224.7759)
  curve K37 (-77.083, 228.9361) -> (-79.8608, 226.3684)
  curve K38 (-75.5537, 230.2778) -> (-77.083, 228.9361)
  curve K39 (-71.6837, 232.5587) -> (-75.5537, 230.2778)
  curve K40 (-50.8, 244.8458) -> (-50.8, 244.8469)
  curve K41 (-50.8, 244.8465) -> (-50.8, 244.8469)
  curve K42 (-50.8, 244.8462) -> (-50.8, 244.8465)
  curve K43 (-50.8, 244.8458) -> (-50.8, 244.8462)
  arc A1 centre (-13.3279, 188.7329) radius 185.6867 clockwise from (-14.1394, 3.048) to (-52.8501, 7.301)
  point P26 (0, 3.048)
  point P33 (-50.8, 237.8015)
  point P35 (-50.8, 237.8015)
  point P40 (-71.6837, 232.5587)
  point P53 (-50.8, 244.8458)
  coincident L3 P26
  perpendicular L3 L4
  coincident P33 P35
  coincident K19 P40
  coincident L6 P53
sketch "Sketch2" plane through (0, 0, 0) normal (0, 1, 0) x axis (1, 0, 0)
  line L1 (-95.6809, 124.1958) -> (-95.6809, 124.2212)
  line L2 (0, 266.7) -> (-50.8, 266.7)
  curve K1 (-58.9317, 239.3909) -> (-50.8, 244.8469)
  curve K2 (-50.8, 244.602) -> (-50.8, 244.8469)
  curve K3 (-50.904, 243.981) -> (-50.8, 244.602)
  curve K4 (-51.2936, 243.3317) -> (-50.904, 243.981)
  curve K5 (-51.734, 242.8041) -> (-51.2936, 243.3317)
  curve K6 (-53.328, 241.5518) -> (-51.734, 242.8041)
  curve K7 (-54.0892, 241.2477) -> (-53.328, 241.5518)
  curve K8 (-58.9317, 239.3909) -> (-54.0892, 241.2477)
  line L3 (-50.8, 266.7) -> (-50.8, 244.8458)
  curve K9 (-52.8501, 7.301) -> (-95.6809, 124.1958)
  curve K10 (-95.6814, 112.4293) -> (-95.6809, 124.1958)
  curve K11 (-95.1681, 95.3068) -> (-95.6814, 112.4293)
  curve K12 (-94.696, 81.2892) -> (-95.1681, 95.3068)
  curve K13 (-94.3798, 70.4902) -> (-94.696, 81.2892)
  curve K14 (-93.5014, 58.328) -> (-94.3798, 70.4902)
  curve K15 (-92.6826, 50.6119) -> (-93.5014, 58.328)
  curve K16 (-87.4432, 33.6688) -> (-92.6826, 50.6119)
  curve K17 (-83.6663, 27.4309) -> (-87.4432, 33.6688)
  curve K18 (-81.2455, 23.6666) -> (-83.6663, 27.4309)
  curve K19 (-79.8608, 22.0741) -> (-81.2455, 23.6666)
  curve K20 (-76.5846, 19.0457) -> (-79.8608, 22.0741)
  curve K21 (-73.7599, 16.6033) -> (-76.5846, 19.0457)
  curve K22 (-65.532, 11.7145) -> (-73.7599, 16.6033)
  curve K23 (-60.3553, 9.483) -> (-65.532, 11.7145)
  curve K24 (-55.4987, 7.9411) -> (-60.3553, 9.483)
  curve K25 (-54.6982, 7.6526) -> (-55.4987, 7.9411)
  curve K26 (-52.8501, 7.301) -> (-54.6982, 7.6526)
  line L4 (-95.6809, 124.2466) -> (-95.6809, 124.2212)
  line L5 (0, 3.048) -> (-6.35, 3.048)
  line L6 (-6.35, 3.048) -> (-14.1394, 3.048)
  curve K27 (-58.9317, 239.3909) -> (-95.6809, 124.2466)
  curve K28 (-95.6814, 136.0132) -> (-95.6809, 124.2466)
  curve K29 (-95.1681, 153.1357) -> (-95.6814, 136.0132)
  curve K30 (-94.696, 167.1533) -> (-95.1681, 153.1357)
  curve K31 (-94.3798, 177.9523) -> (-94.696, 167.1533)
  curve K32 (-93.5014, 190.1145) -> (-94.3798, 177.9523)
  curve K33 (-92.6826, 197.8306) -> (-93.5014, 190.1145)
  curve K34 (-87.4432, 214.7737) -> (-92.6826, 197.8306)
  curve K35 (-83.6663, 221.0115) -> (-87.4432, 214.7737)
  curve K36 (-81.2455, 224.7759) -> (-83.6663, 221.0115)
  curve K37 (-79.8608, 226.3684) -> (-81.2455, 224.7759)
  curve K38 (-76.5846, 229.3968) -> (-79.8608, 226.3684)
  curve K39 (-73.7599, 231.8391) -> (-76.5846, 229.3968)
  curve K40 (-65.833, 236.5491) -> (-73.7599, 231.8391)
  curve K41 (-61.4585, 238.4785) -> (-65.833, 236.5491)
  curve K42 (-58.9317, 239.3909) -> (-61.4585, 238.4785)
  line L7 (0, 3.048) -> (0, 266.7)
  arc A1 centre (-13.3279, 188.7329) radius 185.6867 clockwise from (-14.1394, 3.048) to (-52.8501, 7.301)
  point P52 (-50.8, 244.8458)
  coincident K1 P52
  perpendicular L5 L7
revolve "Revolve1" sketch "Sketch1" AlongAngle 360 bodies "Balon v3.3"
shell "Shell1" innerThickness 3.81
revolve "Revolve2" sketch "Sketch2" AlongAngle 360 bodies "Balon v3.2"
shell "Shell2" innerThickness 3.81
component_from_bodies "Body->Comp1"
component_from_bodies "Body->Comp2"
position "Position1"
remove_instance "RemoveInstance1" bodies "Balon v3"
remove_instance "RemoveInstance2"
move "Move1"
position "Position2" bodies "Balon v3"
sketch "Sketch3" plane through (0, 0, 0) normal (0, 1, 0) x axis (1, 0, 0)
  line L1 (0, 50.8) -> (0, -304.8)
  line L2 (127, 50.8) -> (127, -304.8)
  line L3 (-127, 50.8) -> (-127, -304.8)
  line L4 (139.7, 25.4) -> (-139.7, 25.4)
  line L5 (139.7, -292.1) -> (-139.7, -292.1)
  line L6 (95.25, 50.8) -> (95.25, -304.8)
  vertical L1
  dimension "d6" = 127
  dimension "d12" = -127
  dimension "d17" distance L4 L5 = 317.5
  dimension "d18" = 95.25
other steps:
base_feature "Base Feature1" bodies "Balon v3.3"
base_feature "Base Feature1" bodies "Balon v3.2"
base_feature "Base Feature1" bodies "Balon"
base_feature "Base Feature1" bodies "Balon v3"
base_feature "Base Feature1" bodies "Balon v2"
create_component "CreateComponent1"
remove_body "RemoveBody1"
create_component "CreateComponent2"
remove_body "RemoveBody2"
create_component "CreateComponent3"
remove_body "RemoveBody3" bodies "Balon v3"
create_component "CreateComponent1"
create_component "CreateComponent2"
remove_body "RemoveBody1" bodies "Balon v3"
create_component "CreateComponent3"
remove_body "RemoveBody2" bodies "Balon v3"
named bodies: "Balon", "Balon v2", "Balon v3", "Balon v3.3", "Balon v3.2"

design "Marble Base - Ionic Table Lamp - Ketra Ready - 120V" references "Marble Base - Ionic Table Lamp - 120V"
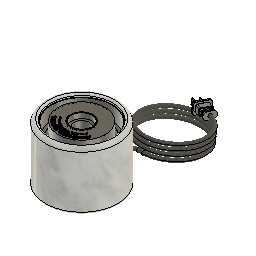
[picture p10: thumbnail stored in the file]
external_derived "ExternalDerived1" bodies "Coiled - SVT (Blk Fabric)", "Body1", "Marble Base", "Body2", "Silicone Gasket", "Plastic Insert"
derived_instance "DerivedInstance1"
derived_instance "DerivedInstance2"
derived_instance "DerivedInstance3"
derived_instance "DerivedInstance4"
derived_instance "DerivedInstance5"
derived_instance "DerivedInstance6"
derived_instance "DerivedInstance7"
derived_instance "DerivedInstance8"
derived_instance "DerivedInstance9"
derived_instance "DerivedInstance10"
derived_instance "DerivedInstance11"
derived_instance "DerivedInstance12"
offset_faces "OffsetFaces1" distance 3.81
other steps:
derived_base_feature "Derived Base Feature1" bodies "Rubber Grommet"
derived_base_feature "Derived Base Feature1" bodies "Neoprene Pad"
derived_base_feature "Derived Base Feature1" bodies "2-Pole Plug End"
derived_base_feature "Derived Base Feature1" bodies "Body1"
derived_base_feature "Derived Base Feature1" bodies "Body1", "Body2"
derived_base_feature "Derived Base Feature1" bodies "Body1"
derived_base_feature "Derived Base Feature1" bodies "Silicone Gasket"
derived_base_feature "Derived Base Feature1" bodies "Plastic Insert"
derived_base_feature "Derived Base Feature1" bodies "Body1"
derived_base_feature "Derived Base Feature1" bodies "Body1"
derived_base_feature "Derived Base Feature1" bodies "Coiled - SVT (Blk Fabric)"
derived_base_feature "Derived Base Feature1" bodies "Marble Base"
create_component "CreateComponent1"
create_component "CreateComponent2"
create_component "CreateComponent3"
create_component "CreateComponent4"
create_component "CreateComponent5"
create_component "CreateComponent6"
create_component "CreateComponent7"
create_component "CreateComponent8"
create_component "CreateComponent9"
create_component "CreateComponent10"
create_component "CreateComponent11"
create_component "CreateComponent12"
named bodies: "Coiled - SVT (Blk Fabric)", "Marble Base", "Body1", "Body2", "Plastic Insert", "Silicone Gasket", "Neoprene Pad", "2-Pole Plug End", "Rubber Grommet"

design "Rubber Grommet"
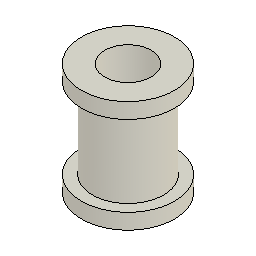
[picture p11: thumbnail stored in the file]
sketch "Sketch1" plane through (0, 0, 0) normal (0, 1, 0) x axis (1, 0, 0)
  line L1 (0, 3.048) -> (0, -12.7)
  line L2 (5.842, 0.508) -> (5.842, -12.7)
  line L3 (3.81, 3.048) -> (3.81, -15.24)
  line L4 (7.62, -12.7) -> (7.62, -15.24)
  line L5 (7.62, 3.048) -> (7.62, 0.508)
  line L6 (7.62, 0.508) -> (5.842, 0.508)
  line L7 (7.62, -12.7) -> (5.842, -12.7)
  line L8 (7.62, -15.24) -> (3.81, -15.24)
  line L9 (7.62, 3.048) -> (3.81, 3.048)
  vertical L1
  collinear L4 L5
revolve "Revolve1" sketch "Sketch1" AlongAngle 360 bodies "Rubber Grommet"
component_from_bodies "Body->Comp"
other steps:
base_feature "Base Feature" bodies "Rubber Grommet"
create_component "CreateComponent1"
remove_body "RemoveBody1"
named bodies: "Rubber Grommet"

design "Marble Base - Ionic Table Lamp - 120V" references "T9 - Bulb", "Arca Tall", "Facet Petite", "T9-5In", "Marble Base - Plastic Insert", "Rubber Grommet", "Neoprene Pad", "2-Pole Plug End", "Trove - TL", "Balon v2", "Chinois", "Marble Base - Silicone Gasket"
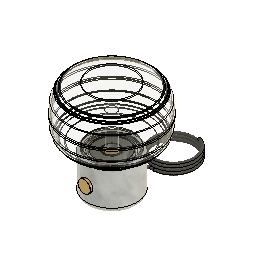
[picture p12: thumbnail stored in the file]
sketch "Sketch1" plane through (0, 0, 0) normal (0, 0, 1) x axis (1, 0, 0)
  circle C1 centre (0, 0) radius 63.5
  point P1 (0, 0)
  point P2 (0, 0)
  coincident P1 P2
extrude "Extrude1" new body sketch "Sketch1" along normal blind 101.6 bodies "Marble Base"
sketch "Sketch2" plane through (0, 0, 101.6) normal (0, 0, 1) x axis (-1, 0, 0)
  circle C1 centre (0, 0) radius 63.5
  circle C2 centre (0, 0) radius 53.975
  concentric C1 C2
  dimension "d3" diameter C2 = 107.95
extrude "Extrude2" cut sketch "Sketch2" profile of C2 against normal blind 34.925
sketch "Sketch3" plane through (0, 0, 66.675) normal (0, 0, 1) x axis (-1, 0, 0)
  circle C1 centre (0, 0) radius 53.975
  circle C2 centre (0, 0) radius 49.276
  point P1 (0, 0)
  point P3 (0, 0)
  coincident P1 P3
  dimension "d6" diameter C2 = 98.552
extrude "Extrude3" cut sketch "Sketch3" profile of C2 against normal blind 45.72
sketch "Sketch4" plane through (0, 0, 0) normal (0, 1, 0) x axis (1, 0, 0)
  circle C1 centre (0, -50.8) radius 3.81
  dimension "d9" diameter C1 = 7.62
extrude "Extrude4" cut sketch "Sketch4" against normal blind 127
sketch "Sketch5" plane through (0, 0, 0) normal (0, 1, 0) x axis (1, 0, 0)
  line L1 (0, -25.4) -> (0, 0)
  line L2 (0, -30.48) -> (0, -25.4)
  circle C1 centre (0, -30.48) radius 5.08
  point P1 (0, 0)
  point P2 (0, 0)
  point P4 (0, -30.48)
  point P5 (0, -30.48)
  coincident P1 P2
  vertical L1
  parallel L1 L2
  coincident P4 P5
  dimension "d12" diameter C1 = 10.16
extrude "Extrude5" cut sketch "Sketch5" profile of C1 along normal blind 114.3
fillet "Fillet1" radius 6.35 3.175 4.064
derived_base_feature "Derived Base Feature1" bodies "Rotary Switch"
derived_base_feature "Derived Base Feature1" bodies "Coiled - SVT (Blk Fabric)"
derived_base_feature "Derived Base Feature1" bodies "Glass Globe"
derived_base_feature "Derived Base Feature1" bodies "Metal Housing"
derived_base_feature "Derived Base Feature1" bodies "Metal Socket Cover"
derived_base_feature "Derived Base Feature1" bodies "Porcelain Socket"
derived_base_feature "Derived Base Feature1" bodies "Brass Dial - Dimmer Knob"
component_from_bodies "Body->Comp1"
offset_faces "OffsetFaces1" distance 12.7
offset_faces "OffsetFaces2" distance -12.7
derived_base_feature "Derived Base Feature1" bodies "Solitaire Petite"
move "Move1"
offset_faces "OffsetFaces1" distance 20.32
move "Move2"
extrude "Extrude6" add of existing geometry blind 25.4
offset_faces "OffsetFaces2" distance -3.81
fillet "Fillet2" radius 2.54
move "Move3"
derived_base_feature "Derived Base Feature2" bodies "Facet Petite"
move "Move4"
offset_faces "OffsetFaces1" distance 2.54
move "Move1"
derived_base_feature "Derived Base Feature1" bodies "Body1"
derived_base_feature "Derived Base Feature1" bodies "Body1"
derived_base_feature "Derived Base Feature1" bodies "Body1"
derived_base_feature "Derived Base Feature1" bodies "Body1"
derived_base_feature "Derived Base Feature1" bodies "Body1"
derived_base_feature "Derived Base Feature1" bodies "Body1", "Body2"
derived_base_feature "Derived Base Feature1" bodies "Body1"
position "Position1"
external_derived "ExternalDerived5" bodies "Plastic Insert"
derived_instance "DerivedInstance15"
offset_faces "OffsetFaces1" distance 3.81
offset_faces "OffsetFaces2" distance -1.0414
move "Move6"
external_derived "ExternalDerived6" sketch "Sketch3" bodies "Silicone Gasket"
derived_instance "DerivedInstance16"
offset_faces "OffsetFaces3" distance -10.795
move "Move1"
move_face "MoveFace1"
position "Position2"
position "Position3"
position "Position4"
position "Position5"
move "Move2"
position "Position6"
offset_faces "OffsetFaces2" distance -7.62
chamfer "Chamfer1" distance 0.381
remove_instance "RemoveInstance1"
remove_instance "RemoveInstance2"
remove_instance "RemoveInstance3"
remove_instance "RemoveInstance4"
move "Move1"
derived_base_feature "Derived Base Feature5" bodies "Oculo Petite"
align "Align1"
external_derived "ExternalDerived8"
derived_base_feature "Derived Base Feature7" bodies "Balon v2"
derived_base_feature "Derived Base Feature8" bodies "Balon v3"
align "Align3"
align "Align4"
external_derived "ExternalDerived10"
component_insert "Component Insert1"
position "Position7"
position "Position8"
derived_base_feature "Derived Base Feature11" bodies "Trove - TL"
move "Move10"
move "Move11"
remove_instance "RemoveInstance5"
split "Split1" bodies "Trove - TL (1)"
remove_body "RemoveBody2"
remove_body "RemoveBody3"
external_derived "ExternalDerived13" bodies "Trove - TL"
derived_instance "DerivedInstance20"
remove_body "RemoveBody4"
remove_body "RemoveBody5"
component_insert "Component Insert2"
component_insert "Component Insert3"
component_from_bodies "Body->Comp2"
remove_body "RemoveBody7"
move "Move12"
move "Move13"
sketch "Sketch6" plane through (0, 0, 97.917) normal (0, 0, 1) x axis (-1, 0, 0)
  circle C1 centre (0, 0) radius 41.275
  circle C2 centre (0, 0) radius 19.685
  arc A1 centre (0, 0) radius 29.3982 clockwise from (-27.6283, 10.0466) to (27.6283, 10.0466)
  arc A2 centre (0, 0) radius 26.2232 clockwise from (-24.6444, 8.9616) to (24.6444, 8.9616)
  arc A3 centre (0, 0) radius 32.5732 clockwise from (-30.6121, 11.1317) to (30.6121, 11.1317)
  arc A4 centre (0, 0) radius 35.7482 clockwise from (-33.596, 12.2167) to (33.596, 12.2167)
  point P1 (0, 0)
  point P3 (0, 0)
  coincident P1 P3
  dimension "d37" = -3.175
  dimension "d38" = 3.175
  dimension "d39" = 6.35
  dimension "d40" Text1-Height = 2.54
  dimension "d41" Text2-Height = 2.54
  dimension "d42" Text3-Height = 2.54
  dimension "d43" Text4-Height = 2.54
extrude "Extrude1" cut sketch "Sketch6" against normal blind 0.254
external_derived "ExternalDerived14" bodies "Rubber Grommet"
derived_instance "DerivedInstance19"
external_derived "ExternalDerived15" bodies "2-Pole Plug End"
derived_instance "DerivedInstance18"
external_derived "ExternalDerived16" bodies "Neoprene Pad"
derived_instance "DerivedInstance17"
position "Position9"
position "Position10"
position "Position11"
position "Position12"
external_derived "ExternalDerived17" bodies "Chinois"
derived_instance "DerivedInstance21"
position "Position13"
move "Move3"
remove_body "RemoveBody8"
component_insert "Component Insert4"
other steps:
derived_base_feature "Derived Base Feature1" bodies "Trove - TL"
derived_base_feature "Derived Base Feature1" bodies "Chinois"
derived_base_feature "Derived Base Feature1" bodies "Rubber Grommet"
derived_base_feature "Derived Base Feature1" bodies "2-Pole Plug End"
derived_base_feature "Derived Base Feature1" bodies "Neoprene Pad"
move "Move1"
base_feature "Base Feature1" bodies "Oculo Petite"
derived_base_feature "Derived Base Feature1" bodies "Plastic Insert"
derived_base_feature "Derived Base Feature1" bodies "Silicone Gasket"
base_feature "Base Feature1" bodies "Marble Base"
move "Move8"
derived_base_feature "Derived Base Feature"
create_component "CreateComponent1"
create_component "CreateComponent2"
create_component "CreateComponent3"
